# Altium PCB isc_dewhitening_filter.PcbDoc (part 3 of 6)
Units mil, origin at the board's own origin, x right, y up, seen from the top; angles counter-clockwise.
Board outline 8440 x 7000 mil, 6 copper layers (Top Layer, MidLayer1, InternalPlane1, Internal Plane 3, InternalPlane2, Bottom Layer); 550 components, 462 nets, 2189 pads, 795 vias.
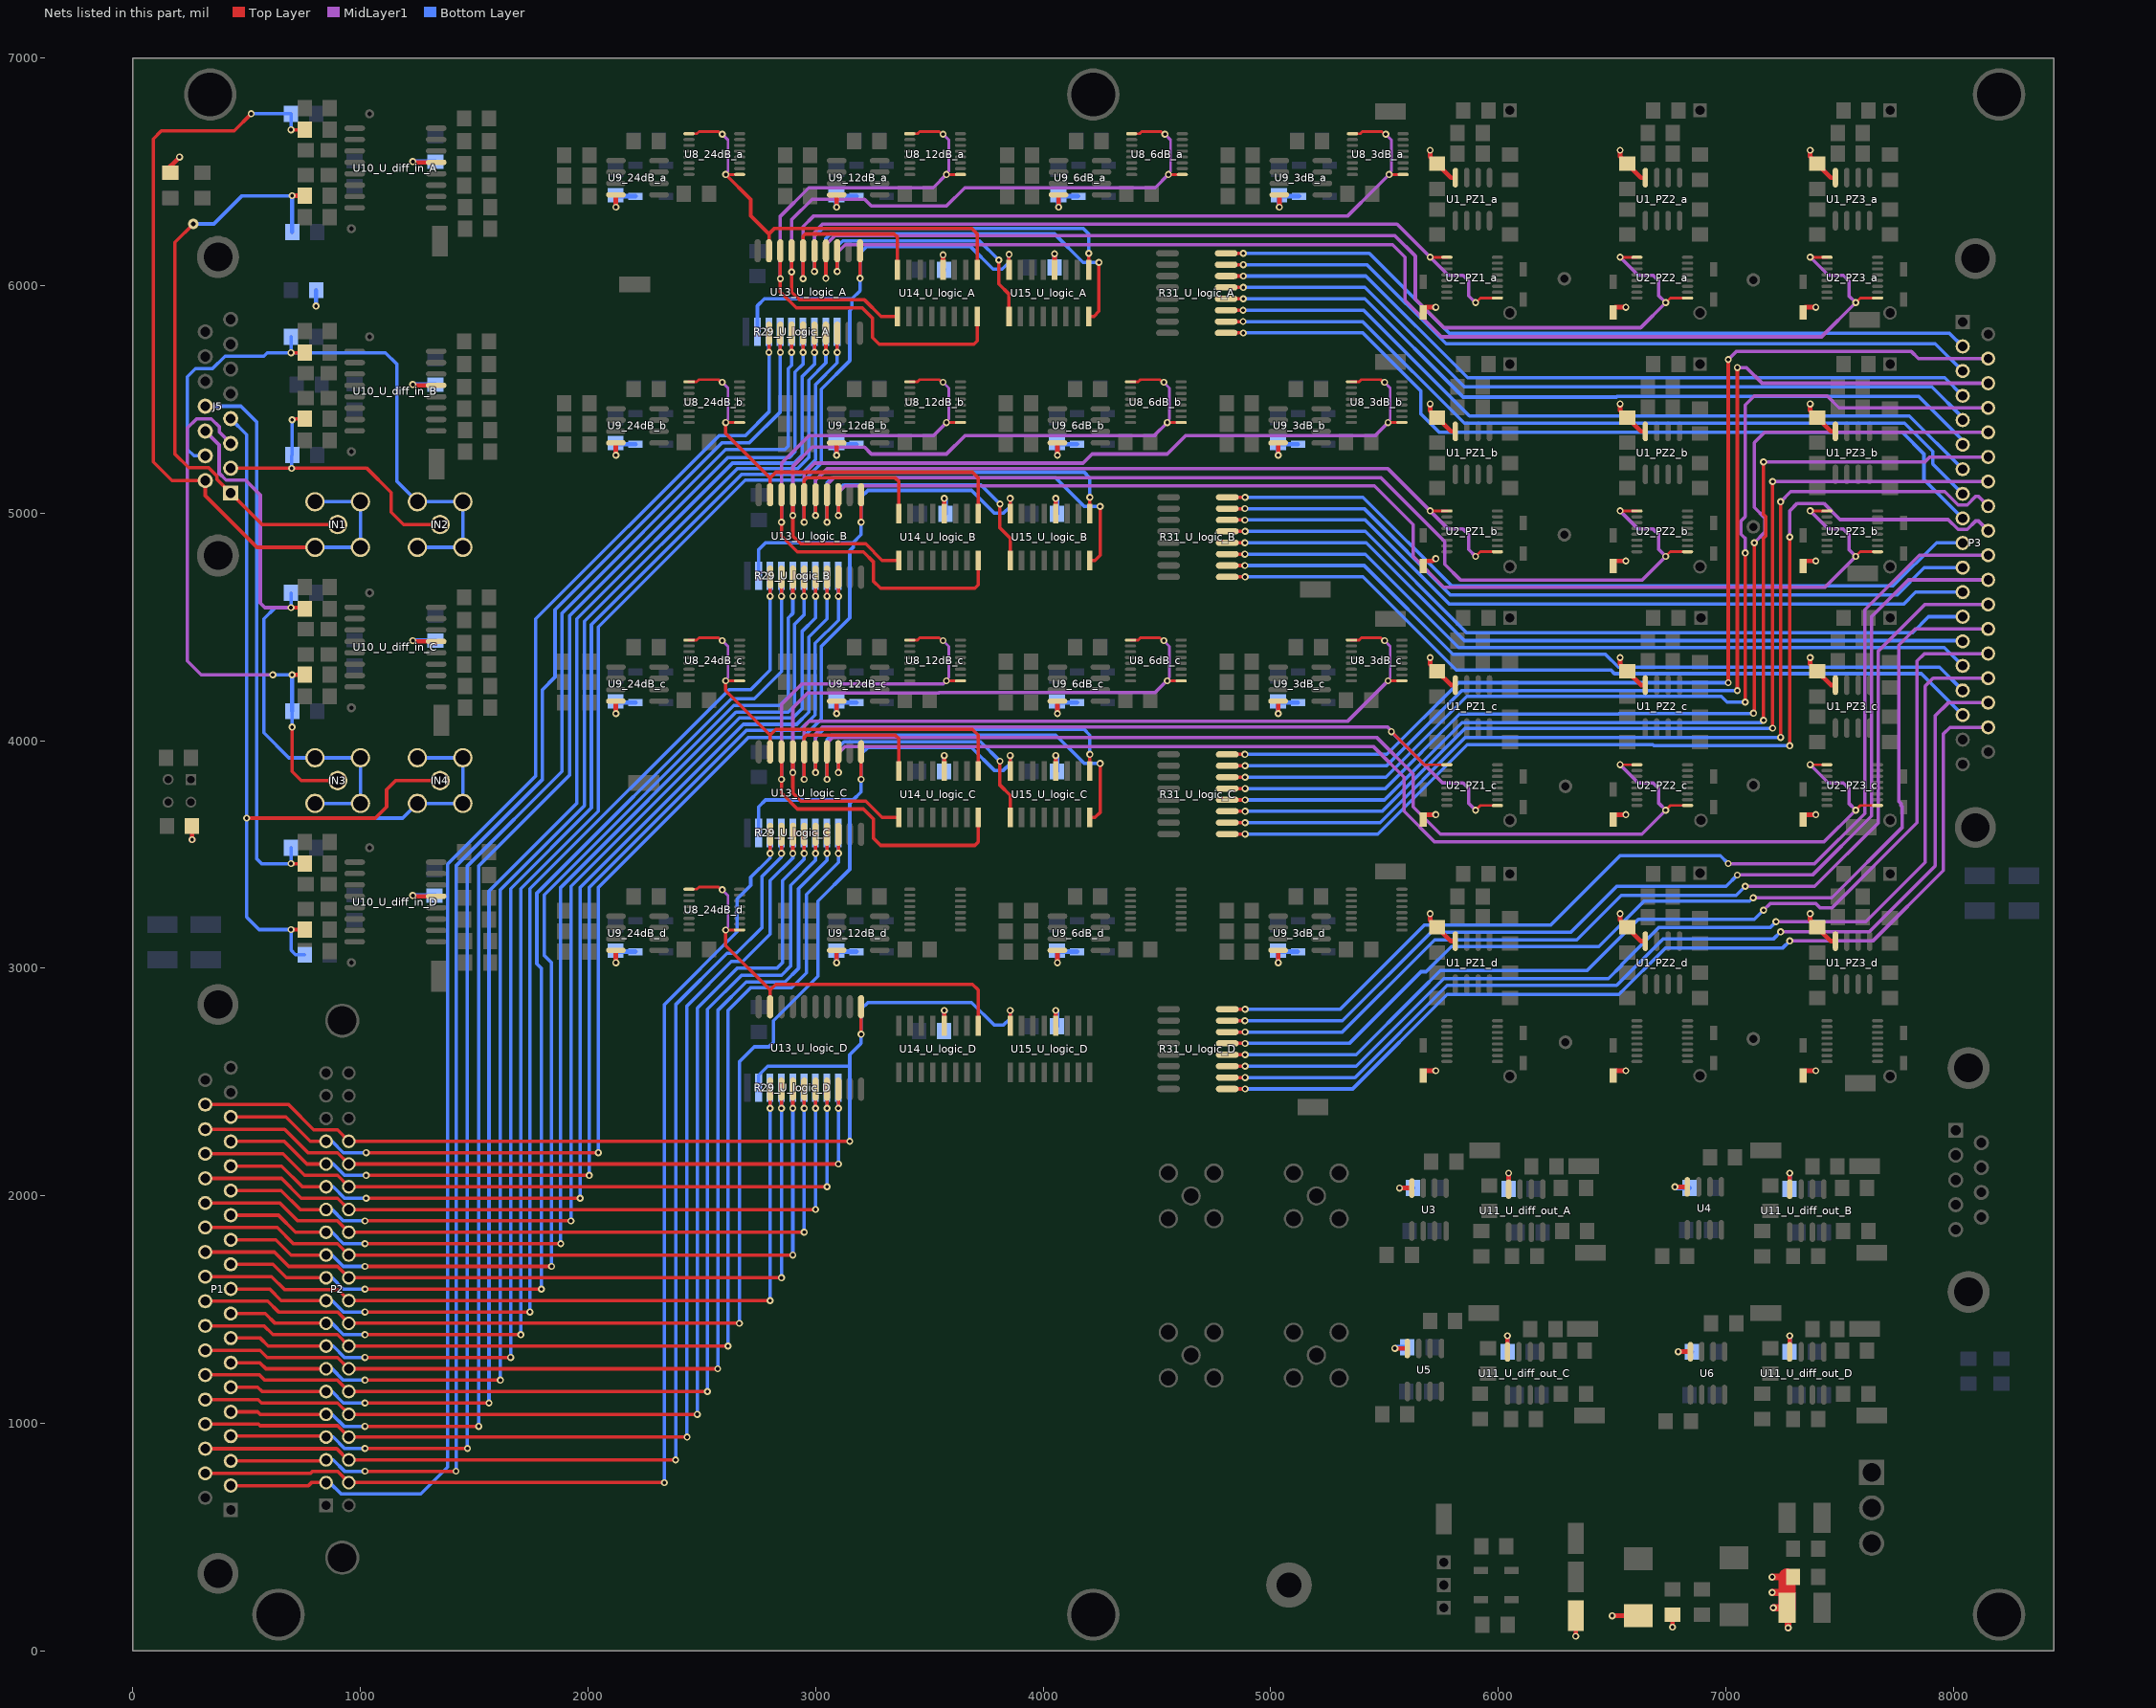
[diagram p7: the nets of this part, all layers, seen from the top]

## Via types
v1: diameter 31, hole 16, Top Layer to Bottom Layer, 794 vias
v2: diameter 45, hole 20, Top Layer to Bottom Layer, 1 vias

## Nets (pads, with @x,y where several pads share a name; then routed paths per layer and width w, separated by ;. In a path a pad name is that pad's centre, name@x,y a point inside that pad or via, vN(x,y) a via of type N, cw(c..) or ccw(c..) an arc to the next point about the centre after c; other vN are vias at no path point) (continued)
-15: C1_PZ1_a.2 C1_PZ1_b.2 C1_PZ1_c.2 C1_PZ1_d.2 C1_PZ2_a.2 C1_PZ2_b.2 C1_PZ2_c.2 C1_PZ2_d.2 C1_PZ3_a.2 C1_PZ3_b.2 C1_PZ3_c.2 C1_PZ3_d.2 C6.2 C9.2 C12.2 C15.2 C22.1 C23.2 C24_3dB_a.2 C24_3dB_b.2 C24_3dB_c.2 C24_3dB_d.2 C24_6dB_a.2 C24_6dB_b.2 C24_6dB_c.2 C24_6dB_d.2 C24_12dB_a.2 C24_12dB_b.2 C24_12dB_c.2 C24_12dB_d.2 C24_24dB_a.2 C24_24dB_b.2 C24_24dB_c.2 C24_24dB_d.2 C29_U_diff_in_A.1 C29_U_diff_in_B.1 C29_U_diff_in_C.1 C29_U_diff_in_D.1 C31_U_diff_out_A.1 C31_U_diff_out_B.1 C31_U_diff_out_C.1 C31_U_diff_out_D.1 C32_U_logic_A.2 C32_U_logic_B.2 C32_U_logic_C.2 C32_U_logic_D.2 C36_U_logic_A.2 C36_U_logic_B.2 C36_U_logic_C.2 C36_U_logic_D.2 D1_PZ1_a.2 D1_PZ1_b.2 D1_PZ1_c.2 D1_PZ1_d.2 D1_PZ2_a.2 D1_PZ2_b.2 D1_PZ2_c.2 D1_PZ2_d.2 D1_PZ3_a.2 D1_PZ3_b.2 D1_PZ3_c.2 D1_PZ3_d.2 D6_3dB_a.2 D6_3dB_b.2 D6_3dB_c.2 D6_3dB_d.2 D6_6dB_a.2 D6_6dB_b.2 D6_6dB_c.2 D6_6dB_d.2 D6_12dB_a.2 D6_12dB_b.2 D6_12dB_c.2 D6_12dB_d.2 D6_24dB_a.2 D6_24dB_b.2 D6_24dB_c.2 D6_24dB_d.2 L2.2 R8.2 R9.2 R36.1 R39.2 TP6.1 U1_PZ1_a.4 U1_PZ1_b.4 U1_PZ1_c.4 U1_PZ1_d.4 U1_PZ2_a.4 U1_PZ2_b.4 U1_PZ2_c.4 U1_PZ2_d.4 U1_PZ3_a.4 U1_PZ3_b.4 U1_PZ3_c.4 U1_PZ3_d.4 U3.4 U4.4 U5.4 U6.4 U9_3dB_a.4 U9_3dB_b.4 U9_3dB_c.4 U9_3dB_d.4 U9_6dB_a.4 U9_6dB_b.4 U9_6dB_c.4 U9_6dB_d.4 U9_12dB_a.4 U9_12dB_b.4 U9_12dB_c.4 U9_12dB_d.4 U9_24dB_a.4 U9_24dB_b.4 U9_24dB_c.4 U9_24dB_d.4 U10_U_diff_in_A.13 U10_U_diff_in_B.13 U10_U_diff_in_C.13 U10_U_diff_in_D.13 U11_U_diff_out_A.4 U11_U_diff_out_B.4 U11_U_diff_out_C.4 U11_U_diff_out_D.4 U14_U_logic_A.4 U14_U_logic_B.4 U14_U_logic_C.4 U14_U_logic_D.4 U15_U_logic_A.4 U15_U_logic_B.4 U15_U_logic_C.4 U15_U_logic_D.4 | length 9805.2
  Top Layer w20: R8.2@165,6495.12 165,6525 v1(205,6565) ; v1(260.12,3565.12) R9.2@260.12,3625 ; v1(1230,3320) 1233.5,3316.5 U10_U_diff_in_D.13@1332.8,3316.5 ; v1(1230,4440) 1233.5,4436.5 U10_U_diff_in_C.13@1332.8,4436.5 ; v1(1230,5565) 1233.5,5561.5 U10_U_diff_in_B.13@1332.8,5561.5 ; v1(1230,6545) 1233.5,6541.5 U10_U_diff_in_A.13@1332.8,6541.5 ; v1@2121,3023 v1(2122.51,3024.51) U9_24dB_d.4@2122.51,3079 ; v1@2121,4118 v1(2122.51,4119.51) U9_24dB_c.4@2122.51,4174 ; v1@2121,5253 v1(2122.51,5254.51) U9_24dB_b.4@2122.51,5309 ; v1@2121,6343 v1(2122.51,6344.51) U9_24dB_a.4@2122.51,6399 ; v1@3091,3023 v1(3092.51,3024.51) U9_12dB_d.4@3092.51,3079 ; v1@3091,4118 v1(3092.51,4119.51) U9_12dB_c.4@3092.51,4174 ; v1@3091,5253 v1(3092.51,5254.51) U9_12dB_b.4@3092.51,5309 ; v1@3091,6343 v1(3092.51,6344.51) U9_12dB_a.4@3092.51,6399 ; U14_U_logic_A.4@3560,6069.36 v1(3560,6135) ; U14_U_logic_D.4@3565,2747.36 v1(3565,2815) ; U14_U_logic_C.4@3565,3867.36 v1(3565,3935) ; U14_U_logic_B.4@3565,4997.36 v1(3565,5065) ; U15_U_logic_A.4@4050,6069.36 v1(4050,6140) ; U15_U_logic_D.4@4055,2747.36 v1(4055,2815) ; U15_U_logic_C.4@4055,3867.36 v1(4055,3935) ; U15_U_logic_B.4@4055,4997.36 v1(4055,5065) ; v1@4061,3023 v1(4062.51,3024.51) U9_6dB_d.4@4062.51,3079 ; v1@4061,4118 v1(4062.51,4119.51) U9_6dB_c.4@4062.51,4174 ; v1@4061,5253 v1(4062.51,5254.51) U9_6dB_b.4@4062.51,5309 ; v1@4066,6343 v1(4067.51,6344.51) U9_6dB_a.4@4067.51,6399 ; v1@5031,3023 v1(5032.51,3024.51) U9_3dB_d.4@5032.51,3079 ; v1@5031,4118 v1(5032.51,4119.51) U9_3dB_c.4@5032.51,4174 ; v1@5031,5253 v1(5032.51,5254.51) U9_3dB_b.4@5032.51,5309 ; v1@5036,6343 v1(5037.51,6344.51) U9_3dB_a.4@5037.51,6399 ; v1@5545.51,1329.49 U5.4@5600,1329.49 ; v1@5565,2035 v1(5565.51,2034.49) U3.4@5620,2034.49 ; D1_PZ1_d.2@5678.07,2550 v1(5725,2550) ; D1_PZ1_c.2@5678.07,3675 v1(5725,3675) ; D1_PZ1_b.2@5678.07,4790 5712.02,4790 5722.02,4800 v1(5725,4800) ; D1_PZ1_a.2@5678.07,5905 v1(5725,5905) ; v1(5700,3240) 5700,3211.12 C1_PZ1_d.2@5731,3180.12 5791.63,3119.49 U1_PZ1_d.4@5811,3119.49 ; v1(5700,4365) 5700,4336.12 C1_PZ1_c.2@5731,4305.12 5791.63,4244.49 U1_PZ1_c.4@5811,4244.49 ; v1(5700,5480) 5700,5451.12 C1_PZ1_b.2@5731,5420.12 5791.63,5359.49 U1_PZ1_b.4@5811,5359.49 ; v1(5700,6595) 5700,6566.12 C1_PZ1_a.2@5731,6535.12 5791.63,6474.49 U1_PZ1_a.4@5811,6474.49 ; U11_U_diff_out_C.4@6040,1314.49 v1(6040,1385) ; U11_U_diff_out_A.4@6045,2029.49 v1(6045,2100) ; v1(6340,65) TP6.1@6340,155 ; v1(6500,155) C23.2@6615,155 ; D1_PZ2_d.2@6513.07,2550 v1(6560,2550) ; D1_PZ2_c.2@6513.07,3675 v1(6560,3675) ; D1_PZ2_b.2@6513.07,4790 v1(6560,4790) ; D1_PZ2_a.2@6513.07,5905 v1(6560,5905) ; v1(6535,3240) 6535,3211.12 C1_PZ2_d.2@6566,3180.12 6626.63,3119.49 U1_PZ2_d.4@6646,3119.49 ; v1(6535,4365) 6535,4336.12 C1_PZ2_c.2@6566,4305.12 6626.63,4244.49 U1_PZ2_c.4@6646,4244.49 ; v1(6535,5480) 6535,5451.12 C1_PZ2_b.2@6566,5420.12 6626.63,5359.49 U1_PZ2_b.4@6646,5359.49 ; v1(6535,6595) 6535,6566.12 C1_PZ2_a.2@6566,6535.12 6626.63,6474.49 U1_PZ2_a.4@6646,6474.49 ; v1(6765,105) C22.1@6765,159.88 ; v1@6775,2040 v1(6775.51,2039.49) U4.4@6830,2039.49 ; v1@6790,1315 v1(6790.49,1315.49) U6.4@6844,1315.49 ; U11_U_diff_out_D.4@7280,1314.49 v1(7280,1385) ; U11_U_diff_out_B.4@7280,2029.49 v1(7280,2100) ; D1_PZ3_d.2@7348.07,2550 v1(7395,2550) ; D1_PZ3_c.2@7348.07,3675 v1(7395,3675) ; D1_PZ3_b.2@7348.07,4790 v1(7395,4790) ; D1_PZ3_a.2@7348.07,5905 v1(7395,5905) ; v1(7370,3240) 7370,3211.12 C1_PZ3_d.2@7401,3180.12 7461.63,3119.49 U1_PZ3_d.4@7481,3119.49 ; v1(7370,4365) 7370,4336.12 C1_PZ3_c.2@7401,4305.12 7461.63,4244.49 U1_PZ3_c.4@7481,4244.49 ; v1(7370,5480) 7370,5451.12 C1_PZ3_b.2@7401,5420.12 7461.63,5359.49 U1_PZ3_b.4@7481,5359.49 ; v1(7370,6595) 7370,6566.12 C1_PZ3_a.2@7401,6535.12 7461.63,6474.49 U1_PZ3_a.4@7481,6474.49
  Top Layer w30: v1@260,3565 v1(260.12,3565.12) ; v1(7203.11,257.5) 7268.23,257.5 ; v1(7203.11,325) R39.2@7294.88,325 ; v1(7208.11,190) 7273.23,190 v1(7273.23,101.77)
  Top Layer w75: L2.2@7268.23,190 R39.2@7268.23,325
  Bottom Layer w20: v1@805.12,5910.12 R36.1@805.12,5980 ; v1(1230,3320) 1230.12,3319.88 C29_U_diff_in_D.1@1330,3319.88 ; v1(1230,4440) 1230.12,4439.88 C29_U_diff_in_C.1@1330,4439.88 ; v1(1230,5565) 1230.12,5564.88 C29_U_diff_in_B.1@1330,5564.88 ; v1(1230,6545) 1230.12,6544.88 C29_U_diff_in_A.1@1330,6544.88 ; v1(2122.51,3024.51) 2121,3026.02 C24_24dB_d.2@2121,3077.88 2125.88,3073 D6_24dB_d.2@2209.07,3073 ; v1(2122.51,4119.51) 2121,4121.02 C24_24dB_c.2@2121,4172.88 2125.88,4168 D6_24dB_c.2@2209.07,4168 ; v1(2122.51,5254.51) 2121,5256.02 C24_24dB_b.2@2121,5307.88 2125.88,5303 D6_24dB_b.2@2209.07,5303 ; v1(2122.51,6344.51) 2121,6346.02 C24_24dB_a.2@2121,6397.88 2125.88,6393 D6_24dB_a.2@2209.07,6393 ; v1(3092.51,3024.51) 3091,3026.02 C24_12dB_d.2@3091,3077.88 3095.88,3073 D6_12dB_d.2@3179.07,3073 ; v1(3092.51,4119.51) 3091,4121.02 C24_12dB_c.2@3091,4172.88 3095.88,4168 D6_12dB_c.2@3179.07,4168 ; v1(3092.51,5254.51) 3091,5256.02 C24_12dB_b.2@3091,5307.88 3095.88,5303 D6_12dB_b.2@3179.07,5303 ; v1(3092.51,6344.51) 3091,6346.02 C24_12dB_a.2@3091,6397.88 3095.88,6393 D6_12dB_a.2@3179.07,6393 ; v1(3560,6135) 3560,6075.12 C32_U_logic_A.2@3565.12,6070 ; v1(3565,2815) v1@3565.12,2814.88 ; v1(3565,5065) 3570.12,5059.88 C32_U_logic_B.2@3570.12,4997.36 ; C32_U_logic_D.2@3565.12,2725 v1@3565.12,2814.88 ; C32_U_logic_C.2@3565.12,3865 v1@3565.12,3934.88 ; v1@3570.12,2809.88 v1@3565.12,2814.88 ; v1(4050,6140) 4050.12,6139.88 C36_U_logic_A.2@4050.12,6070 ; v1(4055,2815) 4060.12,2809.88 C36_U_logic_D.2@4060.12,2745 ; v1(4055,3935) 4060.12,3929.88 C36_U_logic_C.2@4060.12,3865 ; v1(4055,5065) 4060.12,5059.88 C36_U_logic_B.2@4060.12,4997.36 ; v1(4062.51,3024.51) 4061,3026.02 C24_6dB_d.2@4061,3077.88 4065.88,3073 D6_6dB_d.2@4149.07,3073 ; v1(4062.51,4119.51) 4061,4121.02 C24_6dB_c.2@4061,4172.88 4065.88,4168 D6_6dB_c.2@4149.07,4168 ; v1(4062.51,5254.51) 4061,5256.02 C24_6dB_b.2@4061,5307.88 4065.88,5303 D6_6dB_b.2@4149.07,5303 ; v1(4067.51,6344.51) 4066,6346.02 C24_6dB_a.2@4066,6397.88 4070.88,6393 D6_6dB_a.2@4154.07,6393 ; v1(5032.51,3024.51) 5031,3026.02 C24_3dB_d.2@5031,3077.88 5035.88,3073 D6_3dB_d.2@5119.07,3073 ; v1(5032.51,4119.51) 5031,4121.02 C24_3dB_c.2@5031,4172.88 5035.88,4168 D6_3dB_c.2@5119.07,4168 ; v1(5032.51,5254.51) 5031,5256.02 C24_3dB_b.2@5031,5307.88 5035.88,5303 D6_3dB_b.2@5119.07,5303 ; v1(5037.51,6344.51) 5036,6346.02 C24_3dB_a.2@5036,6397.88 5040.88,6393 D6_3dB_a.2@5124.07,6393 ; v1(5545,1330) 5550,1335 C12.2@5599.88,1335 ; v1(5565.51,2034.49) 5566.02,2035 C6.2@5624.88,2035 ; C31_U_diff_out_C.1@6039.88,1315 6039.88,1384.88 v1(6040,1385) ; C31_U_diff_out_A.1@6044.88,2030 6044.88,2099.88 v1(6045,2100) ; v1(6775.51,2039.49) 6780,2035 C9.2@6839.88,2035 ; v1(6790.49,1315.49) 6790.98,1315 C15.2@6849.88,1315 ; C31_U_diff_out_D.1@7279.88,1315 7279.88,1384.88 v1(7280,1385) ; C31_U_diff_out_B.1@7279.88,2030 7279.88,2099.88 v1(7280,2100)
  other v1: 805,5910
A1: U8_24dB_a.1 U8_24dB_a.9 U13_U_logic_A.19 U14_U_logic_A.1 | length 1914.8
  Top Layer w12: U8_24dB_a.9@2443.78,6667.36 2443.95,6667.53 2477.87,6667.53 2487.34,6677 2572.86,6677 2584.86,6665 v1(2590,6665) ; v1(2605,6488.23) U8_24dB_a.1@2666.22,6488.23
  Top Layer w15: v1(2605,6488.23) 2715,6378.23 2715,6307 2795,6227 ; U13_U_logic_A.19@2795,6153.1 2795,6227 ; U14_U_logic_A.1@3710,6069.36 3710,6227 3685,6252 2820,6252 2795,6227
  MidLayer1 w12: v1(2590,6665) 2615,6640 2615,6503.37 2605,6493.37 v1(2605,6488.23)
A2: U8_12dB_a.1 U8_12dB_a.9 U13_U_logic_A.18 U14_U_logic_A.16 | length 2793.6
  Top Layer w12: U8_12dB_a.9@3413.78,6667.36 3413.95,6667.53 3447.87,6667.53 3457.34,6677 3542.86,6677 3554.86,6665 v1(3560,6665) ; v1(3575,6488.23) U8_12dB_a.1@3636.22,6488.23
  Top Layer w15: U13_U_logic_A.18@2845,6153.1 v1(2845,6030) 2845,5972 2915,5902 3205,5902 3250,5857 3250,5772 3280,5742 3695,5742 3710,5757 U14_U_logic_A.16@3710,5864.64
  MidLayer1 w12: v1(3560,6665) 3585,6640 3585,6503.37 3575,6493.37 v1(3575,6488.23)
  MidLayer1 w15: v1(2845,6030) 2845,6305 2970,6430 3516.77,6430 v1(3575,6488.23)
A3: U8_6dB_a.1 U8_6dB_a.9 U13_U_logic_A.17 U14_U_logic_A.9 | length 3090.2
  Top Layer w12: U8_6dB_a.9@4388.78,6667.36 4388.95,6667.53 4422.87,6667.53 4432.34,6677 4517.86,6677 4529.86,6665 v1(4535,6665) ; v1(4550,6488.23) U8_6dB_a.1@4611.22,6488.23
  Top Layer w15: U13_U_logic_A.17@2895,6153.1 v1(2895,6060) 2895,5972 2930,5937 3215,5937 3287.36,5864.64 U14_U_logic_A.9@3360,5864.64
  MidLayer1 w12: v1(4535,6665) 4560,6640 4560,6503.37 4550,6493.37 v1(4550,6488.23)
  MidLayer1 w15: v1(2895,6060) 2895,6290 2985,6380 3215,6380 3245,6350 3575,6350 3655,6430 4491.77,6430 v1(4550,6488.23)
A4: U8_3dB_a.1 U8_3dB_a.9 U13_U_logic_A.16 U14_U_logic_A.8 | length 4062.2
  Top Layer w12: U8_3dB_a.9@5358.78,6667.36 5358.95,6667.53 5392.87,6667.53 5402.34,6677 5487.86,6677 5499.86,6665 v1(5505,6665) ; v1(5520,6488.23) U8_3dB_a.1@5581.22,6488.23
  Top Layer w15: v1(2945,6030) U13_U_logic_A.16@2945,6153.1 2945,6217 2955,6227 3345,6227 3360,6212 U14_U_logic_A.8@3360,6069.36
  MidLayer1 w12: v1(5505,6665) 5530,6640 5530,6503.37 5520,6493.37 v1(5520,6488.23)
  MidLayer1 w15: v1(2945,6030) 2945,6260 2990,6305 5336.77,6305 5461.77,6430 v1(5520,6488.23)
A5: U2_PZ1_a.1 U2_PZ1_a.9 U13_U_logic_A.15 U15_U_logic_A.1 | length 5085.7
  Top Layer w12: v1(5700,6125) 5700.43,6124.57 U2_PZ1_a.1@5773.78,6124.57 ; v1(5900,5925) 5920.43,5945.43 U2_PZ1_a.9@5996.22,5945.43
  Top Layer w15: v1(2995,6062) U13_U_logic_A.15@2995,6153.1 ; U15_U_logic_A.1@4200,6069.36 v1(4200,6142)
  MidLayer1 w15: v1(2995,6062) 2995,6235 3030,6270 5555,6270 v1(5700,6125) 5780,6045 5845,6045 5870,6020 5870,5955 v1(5900,5925)
  Bottom Layer w15: v1(2995,6062) 2995,6217 3030,6252 4175,6252 4200,6227 v1(4200,6142)
A6: U2_PZ2_a.1 U2_PZ2_a.9 U13_U_logic_A.14 U15_U_logic_A.16 | length 6504.2
  Top Layer w12: v1(6535,6125) 6535.43,6124.57 U2_PZ2_a.1@6608.78,6124.57 ; v1(6735,5925) 6755.43,5945.43 U2_PZ2_a.9@6831.22,5945.43
  Top Layer w15: v1(3045,6032) U13_U_logic_A.14@3045,6153.1 ; U15_U_logic_A.16@4200,5864.64 4222.64,5864.64 4245,5887 v1(4245,6102)
  MidLayer1 w15: v1(3045,6032) 3045,6180 3085,6220 5545,6220 5635,6130 5635,5940 5760,5815 6625,5815 v1(6735,5925) 6705,5955 6705,6020 6680,6045 6615,6045 v1(6535,6125)
  Bottom Layer w15: v1(3045,6032) 3045,6207 3065,6227 4050,6227 4175,6102 v1(4245,6102)
A7: U2_PZ3_a.1 U2_PZ3_a.9 U13_U_logic_A.13 U15_U_logic_A.9 | length 6635.9
  Top Layer w12: v1(7370,6125) 7370.43,6124.57 U2_PZ3_a.1@7443.78,6124.57 ; v1(7570,5925) 7590.43,5945.43 U2_PZ3_a.9@7666.22,5945.43
  Top Layer w15: v1(3095,6062) U13_U_logic_A.13@3095,6153.1 ; v1(3805,6112) 3805,6007 3850,5962 U15_U_logic_A.9@3850,5864.64
  MidLayer1 w15: v1(3095,6062) 3095,6145 3130,6180 5535,6180 5590,6125 5590,5935 5750,5775 7420,5775 v1(7570,5925) 7540,5955 7540,6020 7515,6045 7450,6045 v1(7370,6125)
  Bottom Layer w15: v1(3095,6062) 3095,6172 3120,6197 3720,6197 v1(3805,6112)
AN_1: IN1.2 J5.9 R22_U_diff_in_A.1 R33_U_diff_in_A.2 | length 3704.2
  Top Layer w15: v1(520,6755) 445,6680 125,6680 90,6645 90,5225 172.17,5142.83 J5.9@318.11,5142.83 318.11,5076.89 545,4850 IN1.2@800,4850 ; v1(695,6685) R33_U_diff_in_A.2@754.88,6685
  Bottom Layer w15: v1(520,6755) R22_U_diff_in_A.1@694.88,6755 ; v1(695,6685) R22_U_diff_in_A.1@695,6754.88 ; IN1.2@800,4850 IN1.2@1000,4850 IN1.2@1000,5050 IN1.2@800,5050
AN_2: IN2.2 J5.10 R22_U_diff_in_B.1 R33_U_diff_in_B.2 | length 2766
  Top Layer w15: v1(695,5705) R33_U_diff_in_B.2@754.88,5705
  Bottom Layer w15: J5.10@318.11,5251.89 268.11,5251.89 240,5280 240,5600 275,5635 350,5635 405,5690 575,5690 590,5705 v1(695,5705) ; R22_U_diff_in_B.1@695,5774.88 v1(695,5705) ; IN2.2@1250,4850 IN2.2@1450,4850 IN2.2@1450,5050 IN2.2@1250,5050 1160,5140 1160,5655 1110,5705 v1(695,5705)
AN_3: IN3.2 J5.11 R22_U_diff_in_C.1 R33_U_diff_in_C.2 | length 2687.5
  Top Layer w15: v1(695,4585) 749.88,4585 R33_U_diff_in_C.2@754.88,4580
  MidLayer1 w15: J5.11@318.11,5360.94 379.15,5299.9 379.15,5175.49 409.64,5145 495,5145 560,5080 560,4605 580,4585 v1(695,4585)
  Bottom Layer w15: R22_U_diff_in_C.1@695,4649.88 v1(695,4585) 625,4585 575,4535 575,4035 685,3925 IN3.2@800,3925 IN3.2@1000,3925 IN3.2@1000,3725 IN3.2@800,3725
AN_4: IN4.2 J5.12 R22_U_diff_in_D.1 R33_U_diff_in_D.2 | length 3795.9
  Top Layer w15: v1(695,3460) R33_U_diff_in_D.2@754.88,3460
  Bottom Layer w15: J5.12@318.11,5470 475,5470 545,5400 545,3480 565,3460 v1(695,3460) R22_U_diff_in_D.1@695,3529.88 ; 545,3660 1185,3660 IN4.2@1250,3725 IN4.2@1450,3725 IN4.2@1450,3925 IN4.2@1250,3925
AP_1: IN1.1 J5.1 R14_U_diff_in_A.2 R32_U_diff_in_A.2 | length 2596.6
  Top Layer w15: v2(266,6271) 185,6190 185,5260 245,5200 332.74,5200 368.88,5163.86 368.88,5149.35 J5.1@429.92,5088.31 568.23,4950 IN1.1@900,4950
  Top Layer w20: v1(700,6395) R32_U_diff_in_A.2@754.88,6395
  Bottom Layer w15: v2(266,6271) 356,6271 480,6395 v1(700,6395)
  Bottom Layer w20: R14_U_diff_in_A.2@700,6235.12 v1(700,6395)
AP_2: IN2.1 J5.2 R14_U_diff_in_B.2 R32_U_diff_in_B.2 | length 1343.1
  Top Layer w15: J5.2@429.92,5197.36 697.64,5197.36 v1(698,5197) ; v1@698.68,5198.68 1026.32,5198.68 1135,5090 1135,5005 1190,4950 IN2.1@1350,4950 ; v1(700,5410) 705,5415 R32_U_diff_in_B.2@754.88,5415
  Bottom Layer w15: v1(698,5197) 698,5253 700,5255 v1(700,5410)
AP_3: IN3.1 J5.3 R14_U_diff_in_C.2 R32_U_diff_in_C.2 | length 2471.4
  Top Layer w15: v1(700,4060) 700,3865 740,3825 IN3.1@900,3825
  Top Layer w20: v1(700,4290) R32_U_diff_in_C.2@754.88,4290
  MidLayer1 w15: J5.3@429.92,5306.42 380,5356.34 380,5380 345,5415 280,5415 240,5375 240,4350 300,4290 v1(615,4290)
  Bottom Layer w15: v1(615,4290) v1(700,4290) ; v1(700,4060) R14_U_diff_in_C.2@700,4129.88
  Bottom Layer w20: R14_U_diff_in_C.2@700,4130.12 v1(700,4290)
AP_4: IN4.1 J5.4 R14_U_diff_in_D.2 R32_U_diff_in_D.2 | length 3617.6
  Top Layer w15: v1(500,3660) 1065,3660 1115,3710 1115,3785 1155,3825 IN4.1@1350,3825 ; v1(695,3170) R32_U_diff_in_D.2@754.88,3170
  Bottom Layer w15: J5.4@429.92,5415.47 500,5345.39 v1(500,3660) 500,3225 555,3170 v1(695,3170) 695,3080 715,3060 R14_U_diff_in_D.2@754.88,3060
B1: U8_24dB_b.1 U8_24dB_b.9 U13_U_logic_B.19 U14_U_logic_B.1 | length 1898.9
  Top Layer w12: U8_24dB_b.9@2443.78,5577.36 2443.95,5577.53 2477.87,5577.53 2487.34,5587 2572.86,5587 2584.86,5575 v1(2590,5575) ; v1(2605,5398.23) U8_24dB_b.1@2666.22,5398.23
  Top Layer w15: v1(2605,5398.23) 2605,5350 2800,5155 ; U13_U_logic_B.19@2800,5081.1 2800,5155 ; U14_U_logic_B.1@3715,4997.36 3715,5155 3690,5180 2825,5180 2800,5155
  MidLayer1 w12: v1(2590,5575) 2615,5550 2615,5413.37 2605,5403.37 v1(2605,5398.23)
B2: U8_12dB_b.1 U8_12dB_b.9 U13_U_logic_B.18 U14_U_logic_B.16 | length 2771.5
  Top Layer w12: U8_12dB_b.9@3413.78,5577.36 3413.95,5577.53 3447.87,5577.53 3457.34,5587 3542.86,5587 3554.86,5575 v1(3560,5575) ; v1(3575,5398.23) U8_12dB_b.1@3636.22,5398.23
  Top Layer w15: U13_U_logic_B.18@2850,5081.1 v1(2850,4960) 2850,4900 2920,4830 3210,4830 3255,4785 3255,4700 3285,4670 3700,4670 3715,4685 U14_U_logic_B.16@3715,4792.64
  MidLayer1 w12: v1(3560,5575) 3585,5550 3585,5413.37 3575,5403.37 v1(3575,5398.23)
  MidLayer1 w15: v1(2850,4960) 2850,5220 2897.5,5267.5 2970,5340 3516.77,5340 v1(3575,5398.23)
B3: U8_6dB_b.1 U8_6dB_b.9 U13_U_logic_B.17 U14_U_logic_B.9 | length 3614.9
  Top Layer w12: U8_6dB_b.9@4383.78,5577.36 4383.95,5577.53 4417.87,5577.53 4427.34,5587 4512.86,5587 4524.86,5575 v1(4530,5575) ; v1(4545,5398.23) U8_6dB_b.1@4606.22,5398.23
  Top Layer w15: U13_U_logic_B.17@2900,5081.1 v1(2900,4990) 2900,4900 2935,4865 3220,4865 3292.36,4792.64 U14_U_logic_B.9@3365,4792.64
  MidLayer1 w12: v1(4530,5575) 4555,5550 4555,5413.37 4545,5403.37 v1(4545,5398.23)
  MidLayer1 w15: v1(2900,4990) 2900,5205 2985,5290 3215,5290 3245,5260 3575,5260 3655,5340 4491.77,5340 ; 3940,5340 4486.77,5340 v1(4545,5398.23)
B4: U8_3dB_b.1 U8_3dB_b.9 U13_U_logic_B.16 U14_U_logic_B.8 | length 4584.9
  Top Layer w12: U8_3dB_b.9@5353.78,5577.36 5353.95,5577.53 5387.87,5577.53 5397.34,5587 5482.86,5587 5494.86,5575 v1(5500,5575) ; v1(5515,5398.23) U8_3dB_b.1@5576.22,5398.23
  Top Layer w15: v1(2950,4960) U13_U_logic_B.16@2950,5081.1 2950,5145 2960,5155 3350,5155 3365,5140 U14_U_logic_B.8@3365,4997.36
  MidLayer1 w12: v1(5500,5575) 5525,5550 5525,5413.37 5515,5403.37 v1(5515,5398.23)
  MidLayer1 w15: v1(2950,4960) 2950,5175 2995,5220 4175,5220 4215,5260 4545,5260 4625,5340 5456.77,5340 ; 4910,5340 5456.77,5340 ; 5461.77,5340 5456.77,5340 ; v1(5515,5398.23) 5456.77,5340
B5: U2_PZ1_b.1 U2_PZ1_b.9 U13_U_logic_B.15 U15_U_logic_B.1 | length 5085.5
  Top Layer w12: v1(5700,5010) 5700.43,5009.57 U2_PZ1_b.1@5773.78,5009.57 ; v1(5900,4810) 5920.43,4830.43 U2_PZ1_b.9@5996.22,4830.43
  Top Layer w15: v1(3000,4990) U13_U_logic_B.15@3000,5081.1 ; U15_U_logic_B.1@4205,4997.36 v1(4205,5070)
  MidLayer1 w15: v1(3000,4990) 3000,5145 3050,5195 5515,5195 v1(5700,5010) 5780,4930 5845,4930 5870,4905 5870,4840 v1(5900,4810)
  Bottom Layer w15: v1(3000,4990) 3000,5145 3035,5180 4180,5180 4205,5155 v1(4205,5070)
B6: U2_PZ2_b.1 U2_PZ2_b.9 U13_U_logic_B.14 U15_U_logic_B.16 | length 6475.9
  Top Layer w12: v1(6535,5010) 6535.43,5009.57 U2_PZ2_b.1@6608.78,5009.57 ; v1(6735,4810) 6755.43,4830.43 U2_PZ2_b.9@6831.22,4830.43
  Top Layer w15: v1(3050,4960) U13_U_logic_B.14@3050,5081.1 ; U15_U_logic_B.16@4205,4792.64 4227.64,4792.64 4250,4815 v1(4250,5030)
  MidLayer1 w15: v1(3050,4960) 3050,5125 3080,5155 5485,5155 5765,4875 5765,4775 5835,4705 6630,4705 v1(6735,4810) 6705,4840 6705,4905 6680,4930 6615,4930 v1(6535,5010)
  Bottom Layer w15: v1(3050,4960) 3050,5135 3070,5155 4055,5155 4180,5030 v1(4250,5030)
B7: U2_PZ3_b.1 U2_PZ3_b.9 U13_U_logic_B.13 U15_U_logic_B.9 | length 6626.9
  Top Layer w12: v1(7370,5010) 7370.43,5009.57 U2_PZ3_b.1@7443.78,5009.57 ; v1(7570,4810) 7590.43,4830.43 U2_PZ3_b.9@7666.22,4830.43
  Top Layer w15: v1(3100,4990) U13_U_logic_B.13@3100,5081.1 ; v1(3810,5040) 3810,4935 3855,4890 U15_U_logic_B.9@3855,4792.64
  MidLayer1 w15: v1(3100,4990) 3100,5090 3130,5120 5455,5120 5625,4950 5625,4810 5760,4675 7380,4675 7435,4675 v1(7570,4810) 7540,4840 7540,4905 7515,4930 7450,4930 v1(7370,5010)
  Bottom Layer w15: v1(3100,4990) 3100,5100 3125,5125 3725,5125 v1(3810,5040)
BI_0: P1.2 P2.3 R29_U_logic_A.3 U13_U_logic_A.2 | length 6752.5
  Top Layer w15: P1.2@430,727 772,727 785,740 P2.3@849,740 ; v1(2795,5707) U13_U_logic_A.2@2795,5790.9
  Bottom Layer w15: P2.3@849,740 865,740 915,690 1265,690 1382.93,807.93 1382.93,3457.93 1770,3845 1770,4535 2575,5340 2690,5340 2795,5445 v1(2795,5707) ; v1@2794.41,5707.59 R29_U_logic_A.3@2794.41,5797
BI_1: P1.3 P2.5 R29_U_logic_A.4 U13_U_logic_A.3 | length 6763.6
  Top Layer w15: P1.3@430,835 844,835 P2.5@849,840 ; v1(1020,790) v1(1420,790) ; v1(2845,5707) U13_U_logic_A.3@2845,5790.9
  Bottom Layer w15: P2.5@849,840 880,840 930,790 v1(1020,790) ; v1(1420,790) 1420,3450 1800,3830 1800,4225 1855,4280 1855,4575 2590,5310 2710,5310 2845,5445 v1(2845,5707) ; v1@2844.41,5707.59 R29_U_logic_A.4@2844.41,5797
BI_2: P1.4 P2.7 R29_U_logic_A.5 U13_U_logic_A.4 | length 6795.2
  Top Layer w15: P1.4@430,944 845,944 P2.7@849,940 ; v1(1020,890) v1(1470,890) ; v1(2895,5707) U13_U_logic_A.4@2895,5790.9
  Bottom Layer w15: P2.7@849,940 880,940 930,890 v1(1020,890) ; v1(1470,890) 1470,3450 1885,3865 1885,4560 2605,5280 2865,5280 2880,5295 2880,5635 2895,5650 v1(2895,5707) ; v1@2894.41,5707.59 R29_U_logic_A.5@2894.41,5797
BI_3: P1.5 P2.9 R29_U_logic_A.6 U13_U_logic_A.5 | length 6757.5
  Top Layer w15: P1.5@430,1051 549,1051 560,1040 P2.9@849,1040 ; v1(1020,987.5) v1(1520,987.5) ; v1(2945,5707) U13_U_logic_A.5@2945,5790.9
  Bottom Layer w15: P2.9@849,1040 875,1040 927.5,987.5 v1(1020,987.5) ; v1(1520,987.5) 1520,3450 1920,3850 1920,4550 2615,5245 2885,5245 2910,5270 2910,5620 2945,5655 v1(2945,5707) ; v1@2944.41,5707.59 R29_U_logic_A.6@2944.41,5797
BI_4: P1.6 P2.11 R29_U_logic_A.7 U13_U_logic_A.6 | length 6704.4
  Top Layer w15: P1.6@430,1159 549,1159 568,1140 P2.11@849,1140 ; v1(1020,1090) v1(1565,1090) ; v1(2995,5707) U13_U_logic_A.6@2995,5790.9
  Bottom Layer w15: P2.11@849,1140 875,1140 925,1090 v1(1020,1090) ; v1(1565,1090) 1565,3340 1950,3725 1950,4535 2635,5220 2905,5220 2940,5255 2940,5600 2995,5655 v1(2995,5707) ; v1@2994.41,5707.59 R29_U_logic_A.7@2994.41,5797
BI_5: P1.7 P2.13 R29_U_logic_A.8 U13_U_logic_A.7 | length 6654.8
  Top Layer w15: P1.7@430,1267 558,1267 585,1240 P2.13@849,1240 ; v1(1020,1190) v1(1615,1190) ; v1(3045,5707) U13_U_logic_A.7@3045,5790.9
  Bottom Layer w15: P2.13@849,1240 875,1240 925,1190 v1(1020,1190) ; v1(1615,1190) 1615,3345 1984.82,3714.82 1984.82,4524.82 2655,5195 2920,5195 2970,5245 2970,5585 3045,5660 v1(3045,5707) ; v1@3044.41,5707.59 R29_U_logic_A.8@3044.41,5797
BI_6: P1.8 P2.15 R29_U_logic_A.9 U13_U_logic_A.8 | length 6602.2
  Top Layer w15: P1.8@430,1375 560,1375 595,1340 P2.15@849,1340 ; v1(1020,1290) v1(1660,1290) ; v1(3095,5707) U13_U_logic_A.8@3095,5790.9
  Bottom Layer w15: P2.15@849,1340 880,1340 930,1290 v1(1020,1290) ; v1(1660,1290) 1660,3350 2014.82,3704.82 2014.82,4509.82 2675,5170 2935,5170 3000,5235 3000,5565 3095,5660 v1(3095,5707) ; v1@3094.41,5707.59 R29_U_logic_A.9@3094.41,5797
BI_7: P1.9 P2.17 R29_U_logic_A.2 U13_U_logic_A.11 U15_U_logic_A.8 | length 8322.7
  Top Layer w15: P1.9@430,1483 582,1483 625,1440 P2.17@849,1440 ; v1(1020,1390) v1(1705,1390) ; v1(3195,6032) U13_U_logic_A.11@3195,6153.1 ; U15_U_logic_A.8@3850,6069.36 v1(3850,6137)
  Bottom Layer w15: P2.17@849,1440 875,1440 925,1390 v1(1020,1390) ; v1(1705,1390) 1705,3350 2045,3690 2045,4500 2690,5145 2950,5145 3025,5220 3025,5545 3150,5670 3150,5890 3160,5900 3160,5942 ; R29_U_logic_A.2@2744.41,5797 2744.41,5911.41 2775,5942 3160,5942 ; v1(3850,6137) 3850,6102 3820,6072 3780,6072 3680,6172 3225,6172 3195,6142 v1(3195,6032) 3195,5977 3160,5942
BI_8: P1.10 P2.19 R29_U_logic_B.3 U13_U_logic_B.2 | length 5167.8
  Top Layer w15: P1.10@430,1591 601,1591 652,1540 P2.19@849,1540 ; v1(1020,1490) v1(1745,1490) ; v1(2800,4635) U13_U_logic_B.2@2800,4718.9
  Bottom Layer w15: P2.19@849,1540 875,1540 925,1490 v1(1020,1490) ; v1(1745,1490) 1745,3350 2620,4225 2715,4225 2800,4310 v1(2800,4635) ; v1@2799.41,4635.59 R29_U_logic_B.3@2799.41,4725
BI_9: P1.11 P2.21 R29_U_logic_B.4 U13_U_logic_B.3 | length 5140.6
  Top Layer w15: P1.11@430,1699 616,1699 675,1640 P2.21@849,1640 ; v1(1020,1590) v1(1795,1590) ; v1(2850,4635) U13_U_logic_B.3@2850,4718.9
  Bottom Layer w15: P2.21@849,1640 875,1640 925,1590 v1(1020,1590) ; v1(1795,1590) 1795,3000 1775,3020 1775,3330 2630,4185 2730,4185 2850,4305 v1(2850,4635) ; v1@2849.41,4635.59 R29_U_logic_B.4@2849.41,4725
BI_10: P1.12 P2.23 R29_U_logic_B.5 U13_U_logic_B.4 | length 5162.1
  Top Layer w15: P1.12@430,1807 628,1807 695,1740 P2.23@849,1740 ; v1(1020,1690) v1(1840,1690) ; v1(2900,4635) U13_U_logic_B.4@2900,4718.9
  Bottom Layer w15: P2.23@849,1740 875,1740 925,1690 v1(1020,1690) ; v1(1840,1690) 1840,3023.33 1807,3056.33 1807,3322 2640,4155 2843,4155 2880,4192 2880,4540 2900,4560 v1(2900,4635) ; v1@2899.41,4635.59 R29_U_logic_B.5@2899.41,4725
BI_11: P1.13 P2.25 R29_U_logic_B.6 U13_U_logic_B.5 | length 5098
  Top Layer w15: P1.13@430,1915 640,1915 715,1840 P2.25@849,1840 ; v1(1020,1790) v1(1880,1790) ; v1(2950,4635) U13_U_logic_B.5@2950,4718.9
  Bottom Layer w15: P2.25@849,1840 875,1840 925,1790 v1(1020,1790) ; v1(1880,1790) 1880,3355 2650,4125 2880,4125 2908,4153 2908,4513 2950,4555 v1(2950,4635) ; v1@2949.41,4635.59 R29_U_logic_B.6@2949.41,4725
BI_12: P1.14 P2.27 R29_U_logic_B.7 U13_U_logic_B.6 | length 5051.3
  Top Layer w15: P1.14@430,2023 652,2023 735,1940 P2.27@849,1940 ; v1(1020,1890) v1(1925,1890) ; v1(3000,4635) U13_U_logic_B.6@3000,4718.9
  Bottom Layer w15: P2.27@849,1940 875,1940 925,1890 v1(1020,1890) ; v1(1925,1890) 1925,3360 2665,4100 2900,4100 2940,4140 2940,4480 3000,4540 v1(3000,4635) ; v1@2999.41,4635.59 R29_U_logic_B.7@2999.41,4725
BI_13: P1.15 P2.29 R29_U_logic_B.8 U13_U_logic_B.7 | length 4998.8
  Top Layer w15: P1.15@430,2131 654,2131 745,2040 P2.29@849,2040 ; v1(1025,1990) v1(1965,1990) ; v1(3050,4635) U13_U_logic_B.7@3050,4718.9
  Bottom Layer w15: P2.29@849,2040 880,2040 930,1990 v1(1025,1990) ; v1(1965,1990) 1965,3355 2682,4072 2917,4072 2971,4126 2971,4456 3050,4535 v1(3050,4635) ; v1@3049.41,4635.59 R29_U_logic_B.8@3049.41,4725
BI_14: P1.16 P2.31 R29_U_logic_B.9 U13_U_logic_B.8 | length 4951
  Top Layer w15: P1.16@430,2239 666,2239 765,2140 P2.31@849,2140 ; v1(1025,2090) v1(2005,2090) ; v1(3100,4635) U13_U_logic_B.8@3100,4718.9
  Bottom Layer w15: P2.31@849,2140 880,2140 930,2090 v1(1025,2090) ; v1@2005,2085 2005,3355 2695,4045 2929.64,4045 2998,4113.36 2998,4428 3100,4530 v1(3100,4635) ; v1@3099.41,4635.59 R29_U_logic_B.9@3099.41,4725
BI_15: P1.17 P2.33 R29_U_logic_B.2 U13_U_logic_B.11 U15_U_logic_B.8 | length 6666.7
  Top Layer w15: P1.17@430,2347 673,2347 780,2240 P2.33@849,2240 ; v1(1025,2190) v1(2045,2190) ; v1(3200,4960) U13_U_logic_B.11@3200,5081.1 ; U15_U_logic_B.8@3855,4997.36 v1(3855,5065)
  Bottom Layer w15: P2.33@849,2240 875,2240 925,2190 v1(1025,2190) ; v1(2045,2190) 2045,3355 2705,4015 2945,4015 3025,4095 3025,4415 3150,4540 3150,4835 3165,4850 3165,4870 ; R29_U_logic_B.2@2749.41,4725 2749.41,4839.41 2780,4870 3165,4870 ; v1(3855,5065) 3855,5030 3825,5000 3785,5000 3685,5100 3230,5100 3200,5070 v1(3200,4960) 3200,4905 3165,4870
BI_16: P1.21 P2.4 R29_U_logic_C.3 U13_U_logic_C.2 | length 5172.4
  Top Layer w15: P1.21@318,781 781,781 790,790 899,790 P2.4@949,740 v1(2335,740) ; v1(2800,3505) U13_U_logic_C.2@2800,3588.9
  Bottom Layer w15: v1(2335,740) 2335,2840 2655,3160 2655,3305 2715,3365 2715,3400 2800,3485 v1(2800,3505) ; v1@2799.41,3505.59 R29_U_logic_C.3@2799.41,3595
BI_17: P1.22 P2.6 R29_U_logic_C.4 U13_U_logic_C.3 | length 5141.6
  Top Layer w15: P1.22@318,889 896,889 945,840 P2.6@949,840 v1(2385,840) ; v1(2850,3505) U13_U_logic_C.3@2850,3588.9
  Bottom Layer w15: v1(2385,840) 2385,2840 2611.33,3066.33 2651.33,3066.33 2765,3180 2765,3405 2850,3490 v1(2850,3505) ; v1@2849.41,3505.59 R29_U_logic_C.4@2849.41,3595
BI_18: P1.23 P2.8 R29_U_logic_C.5 U13_U_logic_C.4 | length 5100.8
  Top Layer w15: P1.23@318,997 553,997 560,990 899,990 P2.8@949,940 v1(2435,940) ; v1(2900,3505) U13_U_logic_C.4@2900,3588.9
  Bottom Layer w15: v1(2435,940) 2435,2835 2630,3030 2680,3030 2800,3150 2800,3385 2900,3485 v1(2900,3505) ; v1@2899.41,3505.59 R29_U_logic_C.5@2899.41,3595
BI_19: P1.24 P2.10 R29_U_logic_C.6 U13_U_logic_C.5 | length 5125
  Top Layer w15: P1.24@318,1105 550,1105 565,1090 900,1090 949,1041 P2.10@949,1040 v1(2480,1040) ; v1(2950,3505) U13_U_logic_C.5@2950,3588.9
  Bottom Layer w15: v1(2480,1040) 2480,2825 2655,3000 2830,3000 2855,3025 2855,3385 2950,3480 v1(2950,3505) ; v1@2949.41,3505.59 R29_U_logic_C.6@2949.41,3595
BI_20: P1.25 P2.12 R29_U_logic_C.7 U13_U_logic_C.6 | length 5074.8
  Top Layer w15: P1.25@318,1213 557,1213 580,1190 899,1190 P2.12@949,1140 v1(2525,1140) ; v1(3000,3505) U13_U_logic_C.6@3000,3588.9
  Bottom Layer w15: v1(2525,1140) 2525,2820 2675,2970 2850,2970 2890,3010 2890,3365 3000,3475 v1(3000,3505) ; v1@2999.41,3505.59 R29_U_logic_C.7@2999.41,3595
BI_21: P1.26 P2.14 R29_U_logic_C.8 U13_U_logic_C.7 | length 5022.3
  Top Layer w15: P1.26@318,1321 559,1321 590,1290 899,1290 P2.14@949,1240 v1(2570,1240) ; v1(3050,3505) U13_U_logic_C.7@3050,3588.9
  Bottom Layer w15: v1(2570,1240) 2570,2815 2695,2940 2865,2940 2925,3000 2925,3350 3050,3475 v1(3050,3505) ; v1@3049.41,3505.59 R29_U_logic_C.8@3049.41,3595
BI_22: P1.27 P2.16 R29_U_logic_C.9 U13_U_logic_C.8 | length 4978.5
  Top Layer w15: P1.27@318,1429 576,1429 615,1390 899,1390 P2.16@949,1340 v1(2615,1340) ; v1(3100,3505) U13_U_logic_C.8@3100,3588.9
  Bottom Layer w15: v1(2615,1340) 2615,2815 2715,2915 2895,2915 2960,2980 2960,3325 3100,3465 v1(3100,3505) ; v1@3099.41,3505.59 R29_U_logic_C.9@3099.41,3595
BI_23: P1.28 P2.18 R29_U_logic_C.2 U13_U_logic_C.11 U15_U_logic_C.8 | length 6634.5
  Top Layer w15: P1.28@318,1537 593,1537 640,1490 899,1490 P2.18@949,1440 v1(2665,1440) ; v1(3200,3830) U13_U_logic_C.11@3200,3951.1 ; U15_U_logic_C.8@3855,3867.36 v1(3855,3935)
  Bottom Layer w15: v1(2665,1440) 2665,2590 2730,2655 2795,2655 2815,2675 2815,2770 2955,2910 3010,2965 3010,3295 3150,3435 3150,3725 3165,3740 ; R29_U_logic_C.2@2749.41,3595 2749.41,3709.41 2780,3740 3165,3740 ; v1(3855,3935) 3855,3900 3825,3870 3785,3870 3685,3970 3230,3970 3200,3940 v1(3200,3830) 3200,3775 3165,3740
BI_24: P1.29 P2.20 R29_U_logic_D.3 U13_U_logic_D.2 | length 3543.8
  Top Layer w15: P1.29@318,1645 610,1645 667,1588 901,1588 P2.20@949,1540 v1(2800,1540) ; v1(2800,2385) U13_U_logic_D.2@2800,2468.9
  Bottom Layer w15: v1@2799.41,2385.59 R29_U_logic_D.3@2799.41,2475 ; v1(2800,1540) v1(2800,2385)
BI_25: P1.30 P2.22 R29_U_logic_D.4 U13_U_logic_D.3 | length 3497.1
  Top Layer w15: P1.30@318,1753 622,1753 685,1690 899,1690 P2.22@949,1640 v1(2850,1640) ; v1(2850,2385) U13_U_logic_D.3@2850,2468.9
  Bottom Layer w15: v1@2849.41,2385.59 R29_U_logic_D.4@2849.41,2475 ; v1(2850,1640) v1(2850,2385)
BI_26: P1.31 P2.24 R29_U_logic_D.5 U13_U_logic_D.4 | length 3450.4
  Top Layer w15: P1.31@318,1861 634,1861 705,1790 899,1790 P2.24@949,1740 v1(2900,1740) ; v1(2900,2385) U13_U_logic_D.4@2900,2468.9
  Bottom Layer w15: v1@2899.41,2385.59 R29_U_logic_D.5@2899.41,2475 ; v1(2900,1740) v1(2900,2385)
BI_27: P1.32 P2.26 R29_U_logic_D.6 U13_U_logic_D.5 | length 3403.7
  Top Layer w15: P1.32@318,1969 646,1969 725,1890 899,1890 P2.26@949,1840 v1(2950,1840) ; v1(2950,2385) U13_U_logic_D.5@2950,2468.9
  Bottom Layer w15: v1@2949.41,2385.59 R29_U_logic_D.6@2949.41,2475 ; v1(2950,1840) v1(2950,2385)
BI_28: P1.33 P2.28 R29_U_logic_D.7 U13_U_logic_D.6 | length 3357.1
  Top Layer w15: P1.33@318,2077 653,2077 740,1990 899,1990 P2.28@949,1940 v1(3000,1940) ; v1(3000,2385) U13_U_logic_D.6@3000,2468.9
  Bottom Layer w15: v1@2999.41,2385.59 R29_U_logic_D.7@2999.41,2475 ; v1(3000,1940) v1(3000,2385)
BI_29: P1.34 P2.30 R29_U_logic_D.8 U13_U_logic_D.7 | length 3310.4
  Top Layer w15: P1.34@318,2185 660,2185 755,2090 899,2090 P2.30@949,2040 v1(3050,2040) ; v1(3050,2385) U13_U_logic_D.7@3050,2468.9
  Bottom Layer w15: v1@3049.41,2385.59 R29_U_logic_D.8@3049.41,2475 ; v1(3050,2040) v1(3050,2385)
BI_30: P1.35 P2.32 R29_U_logic_D.9 U13_U_logic_D.8 | length 3263.7
  Top Layer w15: P1.35@318,2293 667,2293 770,2190 899,2190 P2.32@949,2140 v1(3100,2140) ; v1(3100,2385) U13_U_logic_D.8@3100,2468.9
  Bottom Layer w15: v1@3099.41,2385.59 R29_U_logic_D.9@3099.41,2475 ; v1(3100,2140) v1(3100,2385)
BI_31: P1.36 P2.34 R29_U_logic_D.2 U13_U_logic_D.11 U15_U_logic_D.8 | length 4916.2
  Top Layer w15: P1.36@318,2401 684,2401 795,2290 899,2290 P2.34@949,2240 v1(3150,2240) ; v1(3200,2710) U13_U_logic_D.11@3200,2831.1 ; U15_U_logic_D.8@3855,2747.36 v1(3855,2815)
  Bottom Layer w15: R29_U_logic_D.2@2749.41,2475 2749.41,2529.41 2790,2570 3150,2570 ; v1(3150,2240) 3150,2620 3200,2670 v1(3200,2710) 3200,2820 3230,2850 3685,2850 3785,2750 3825,2750 3855,2780 v1(3855,2815)
BO_0: P3.2 R31_U_logic_A.16 | length 3405.5
  Top Layer w15: R31_U_logic_A.16@4803.94,6142 v1(4879,6142)
  Bottom Layer w15: v1(4879,6142) 5433,6142 5785,5790 7983,5790 P3.2@8040,5733
BO_1: P3.3 R31_U_logic_A.15 | length 3429.5
  Top Layer w15: R31_U_logic_A.15@4803.94,6092 v1(4879,6092)
  Bottom Layer w15: v1(4879,6092) 5423,6092 5770,5745 7920,5745 P3.3@8040,5625
BO_2: P3.4 R31_U_logic_A.14 | length 3453.9
  Top Layer w15: R31_U_logic_A.14@4803.94,6042 v1(4879,6042)
  Bottom Layer w15: v1(4879,6042) 5418,6042 5865,5595 7961,5595 P3.4@8040,5516
BO_3: P3.5 R31_U_logic_A.13 | length 3484
  Top Layer w15: R31_U_logic_A.13@4803.94,5992 v1(4879,5992)
  Bottom Layer w15: v1(4879,5992) 5413,5992 5850,5555 7905,5555 8040,5420 P3.5@8040,5409
BO_4: P3.6 R31_U_logic_A.12 | length 3515.2
  Top Layer w15: R31_U_logic_A.12@4803.94,5942 v1(4879,5942)
  Bottom Layer w15: v1(4879,5942) 5413,5942 5845,5510 6518.33,5510 6521.33,5513 7847,5513 8040,5320 P3.6@8040,5301
BO_5: P3.7 R31_U_logic_A.11 | length 3525.6
  Top Layer w15: R31_U_logic_A.11@4803.94,5892 v1(4878,5892)
  Bottom Layer w15: v1(4878,5892) 5408,5892 5873,5427 7806,5427 P3.7@8040,5193
BO_6: P3.8 R31_U_logic_A.10 | length 3614.3
  Top Layer w15: R31_U_logic_A.10@4771.46,5842 v1(4878,5842)
  Bottom Layer w15: v1(4878,5842) 5403,5842 5850,5395 7785,5395 7909,5271 7909,5216 P3.8@8040,5085
BO_7: P3.9 R31_U_logic_A.9 | length 3699.4
  Top Layer w15: R31_U_logic_A.9@4803.94,5792 v1(4879,5792)
  Bottom Layer w15: v1(4879,5792) 5404.67,5792 5660,5536.67 5660,5435 5740,5355 7775,5355 7870,5260 7870,5147 P3.9@8040,4977
BO_8: P3.10 R31_U_logic_B.16 | length 3504.2
  Top Layer w15: R31_U_logic_B.16@4776.46,5070 v1(4887,5070)
  Bottom Layer w15: v1(4887,5070) 5405,5070 5795,4680 7735,4680 7925,4870 8039,4870 P3.10@8040,4869
BO_9: P3.11 R31_U_logic_B.15 | length 3471.1
  Top Layer w15: R31_U_logic_B.15@4776.46,5020 v1(4886,5020)
  Bottom Layer w15: v1(4886,5020) 5410,5020 5790,4640 7750,4640 7871,4761 P3.11@8040,4761
BO_10: P3.12 R31_U_logic_B.14 | length 3438.8
  Top Layer w15: R31_U_logic_B.14@4776.46,4970 v1(4886,4970)
  Bottom Layer w15: v1(4886,4970) 5415,4970 5785,4600 7780,4600 7833,4653 P3.12@8040,4653
BO_11: P3.13 R31_U_logic_B.13 | length 3476.9
  Top Layer w15: R31_U_logic_B.13@4776.46,4920 v1(4887,4920)
  Bottom Layer w15: v1(4887,4920) 5415,4920 5860,4475 7820,4475 7890,4545 P3.13@8040,4545
BO_12: P3.14 R31_U_logic_B.12 | length 3442.9
  Top Layer w15: R31_U_logic_B.12@4776.46,4870 v1(4886,4870)
  Bottom Layer w15: v1(4886,4870) 5420,4870 5850,4440 8037,4440 P3.14@8040,4437
BO_13: P3.15 R31_U_logic_B.11 | length 3466.9
  Top Layer w15: R31_U_logic_B.11@4776.46,4820 v1(4886,4820)
  Bottom Layer w15: v1(4886,4820) 5415,4820 5825,4410 7959,4410 P3.15@8040,4329
BO_14: P3.16 R31_U_logic_B.10 | length 3504.9
  Top Layer w15: R31_U_logic_B.10@4776.46,4770 v1(4886,4770)
  Bottom Layer w15: v1(4886,4770) 5410,4770 5800,4380 6470,4380 6527,4323 7915,4323 7938,4323 P3.16@8040,4221 P3.16@8040,4235
BO_15: P3.17 R31_U_logic_B.9 | length 3515
  Top Layer w15: R31_U_logic_B.9@4776.46,4720 v1(4887,4720)
  Bottom Layer w15: v1(4887,4720) 5405,4720 5815,4310 6495,4310 6510,4295 7858,4295 P3.17@8040,4113
BO_16: P3.21 R31_U_logic_C.16 | length 4953.4
  Top Layer w15: R31_U_logic_C.16@4776.46,3940 R31_U_logic_C.16@4808.94,3940 v1(4886,3940) ; v1(7010,4255) v1(7010,5675)
  MidLayer1 w15: v1(7010,5675) 7045,5710 7815,5710 7846,5679 P3.21@8152,5679
  Bottom Layer w15: v1(4886,3940) 5510.67,3940 5825.67,4255 v1(7010,4255)
BO_17: P3.22 R31_U_logic_C.15 | length 4960.8
  Top Layer w15: R31_U_logic_C.15@4776.46,3890 v1(4887,3890) ; v1(7050,4220) v1(7050,5640)
  MidLayer1 w15: v1(7050,5640) 7090,5640 7159,5571 P3.22@8152,5571
  Bottom Layer w15: v1(4887,3890) 5509,3890 5839,4220 v1(7050,4220)
BO_18: P3.23 R31_U_logic_C.14 | length 4892.8
  Top Layer w15: R31_U_logic_C.14@4776.46,3840 v1(4887,3840) ; v1(7085,4170) v1(7085,4825)
  MidLayer1 w15: v1(7085,4825) 7085,4890 ; 7085,4889 7066,4908 7066,4965.68 7085,4984.68 7085,5475 7125,5515 7445,5515 7497,5463 P3.23@8152,5463
  Bottom Layer w15: v1(4887,3840) 5506,3840 5861,4195 6980,4195 7005,4170 v1(7085,4170)
BO_19: P3.24 R31_U_logic_C.13 | length 4765.2
  Top Layer w15: R31_U_logic_C.13@4776.46,3790 v1(4887,3790) ; v1@7120,4870 v1(7125,4870) 7125,4125 v1(7121,4121)
  MidLayer1 w15: v1@7120,4870 v1(7125,4870) 7170,4915 7170,4980 7125,5025 7125,5310 7170,5355 P3.24@8152,5355
  Bottom Layer w15: v1(4887,3790) 5503,3790 5830,4117 6527.67,4117 6530.67,4120 7120,4120 v1(7121,4121)
BO_20: P3.25 R31_U_logic_C.12 | length 4672.9
  Top Layer w15: R31_U_logic_C.12@4776.46,3740 v1(4887,3740) ; v1(7165,4090) 7165,4890 7175,4900 7175,4985 7165,4995 v1(7165,5225)
  MidLayer1 w15: v1(7165,5225) 7874,5225 7896,5247 P3.25@8152,5247
  Bottom Layer w15: v1(4887,3740) 5500,3740 5840,4080 7155,4080 v1(7165,4090)
BO_21: P3.26 R31_U_logic_C.11 | length 4610.7
  Top Layer w15: R31_U_logic_C.11@4776.46,3690 v1(4887,3690) ; v1(7205,4055) v1(7205,5139)
  MidLayer1 w15: v1(7205,5139) P3.26@8152,5139
  Bottom Layer w15: v1(4887,3690) 5490,3690 5855,4055 v1(7205,4055)
BO_22: P3.27 R31_U_logic_C.10 | length 4641.7
  Top Layer w15: R31_U_logic_C.10@4776.46,3640 v1(4887,3640) ; v1(7240,4015) v1(7240,5050)
  MidLayer1 w15: v1(7240,5050) 7285,5095 7961.41,5095 8019.91,5036.5 8060.09,5036.5 8097.08,5073.49 8109.51,5073.49 P3.27@8152,5031
  Bottom Layer w15: v1(4887,3640) 5480,3640 5855,4015 v1(7240,4015)
BO_23: P3.28 R31_U_logic_C.9 | length 4666.4
  Top Layer w15: R31_U_logic_C.9@4776.46,3590 v1(4887,3590) ; v1(7280,3978) v1(7280,4895)
  MidLayer1 w15: v1(7280,4895) 7280,5010 7313,5043 7430.33,5043 7501.33,4972 7976.41,4972 8019.91,4928.5 8060.09,4928.5 8097.08,4965.49 8109.51,4965.49 P3.28@8152,4923
  Bottom Layer w15: v1(4887,3590) 5470,3590 5863,3983 6678.67,3983 6683.67,3978 v1(7280,3978)
BO_24: P3.29 R31_U_logic_D.16 | length 4755.2
  Top Layer w15: R31_U_logic_D.16@4776.46,2820 R31_U_logic_D.16@4808.94,2820 v1(4887,2820)
  MidLayer1 w15: v1(7010,3460) 7390,3460 7610,3680 7610,4575 7850,4815 P3.29@8152,4815
  Bottom Layer w15: v1(4887,2820) 5305,2820 5675,3190 6230,3190 6535,3495 6975,3495 v1(7010,3460)
BO_25: P3.30 R31_U_logic_D.15 | length 4690.4
  Top Layer w15: R31_U_logic_D.15@4776.46,2770 v1(4886,2770)
  MidLayer1 w15: v1(7050,3410) 7060,3410 7380,3410 7640,3670 7640,4545 7802,4707 P3.30@8152,4707
  Bottom Layer w15: v1(4886,2770) 5315,2770 5702.82,3157.82 6317.82,3157.82 6520,3360 7000,3360 v1(7050,3410)
BO_26: P3.31 R31_U_logic_D.14 | length 4596.1
  Top Layer w15: R31_U_logic_D.14@4776.46,2720 v1(4887,2720)
  MidLayer1 w15: v1(7085,3360) 7390,3360 7670,3640 7670,4395 7795,4520 7874,4599 P3.31@8152,4599
  Bottom Layer w15: v1(4887,2720) 5315,2720 5670,3075 5720,3125 5780,3125 6345,3125 6540,3320 7045,3320 v1(7085,3360)
BO_27: P3.32 R31_U_logic_D.13 | length 4619.7
  Top Layer w15: R31_U_logic_D.13@4776.46,2670 v1(4887,2670)
  MidLayer1 w15: v1(7120,3310) 7465,3310 7775,3620 7775,3710 7769,3716 7769,3724.67 7760,3733.67 7760,4420 7831,4491 P3.32@8152,4491
  Bottom Layer w15: v1(4887,2670) 5345,2670 5660,2985 5683,2985 5793.74,3095.74 6440.74,3095.74 6640,3295 7103.21,3295 7118.21,3310 v1(7120,3310)
BO_28: P3.33 R31_U_logic_D.12 | length 4538.3
  Top Layer w15: R31_U_logic_D.12@4776.46,2620 v1(4887,2620)
  MidLayer1 w15: v1(7165,3255) 7195,3285 7395,3285 7415,3265 7465,3265 7840,3640 7840,4350 7873,4383 P3.33@8152,4383
  Bottom Layer w15: v1(4887,2620) 5375,2620 5650,2895 5745,2990 6390,2990 6615,3215 7125,3215 v1(7165,3255)
BO_29: P3.34 R31_U_logic_D.11 | length 4537.9
  Top Layer w15: R31_U_logic_D.11@4776.46,2570 v1(4887,2570)
  MidLayer1 w15: v1(7220,3205) 7615,3205 7875,3465 7875,4240 7910,4275 P3.34@8152,4275
  Bottom Layer w15: v1(4887,2570) 5375,2570 5415,2610 5760,2955 6483.67,2955 6543,3014.33 6543,3018 6705,3180 7195,3180 v1(7220,3205)
BO_30: P3.35 R31_U_logic_D.10 | length 4444.4
  Top Layer w15: R31_U_logic_D.10@4776.46,2520 v1(4887,2520)
  MidLayer1 w15: v1(7240,3160) 7630,3160 7920,3450 7920,4110 7977,4167 P3.35@8152,4167
  Bottom Layer w15: v1(4887,2520) 5370,2520 5775,2925 6520,2925 6725,3130 7210,3130 v1(7240,3160)
BO_31: P3.36 R31_U_logic_D.9 | length 4385.2
  Top Layer w15: R31_U_logic_D.9@4776.46,2470 v1(4887,2470)
  MidLayer1 w15: v1(7280,3120) 7645,3120 7955,3430 7955,4030 7984,4059 P3.36@8152,4059
  Bottom Layer w15: v1(4887,2470) 5360,2470 5775,2885 6530,2885 6735,3090 7250,3090 v1(7280,3120)
C1: U8_24dB_c.1 U8_24dB_c.9 U13_U_logic_C.19 U14_U_logic_C.1 | length 1893.9
  Top Layer w12: U8_24dB_c.9@2443.78,4442.36 2443.95,4442.53 2477.87,4442.53 2487.34,4452 2572.86,4452 2584.86,4440 v1(2590,4440) ; v1(2605,4263.23) U8_24dB_c.1@2666.22,4263.23
  Top Layer w15: v1(2605,4263.23) 2605,4220 2800,4025 ; U13_U_logic_C.19@2800,3951.1 2800,4025 ; U14_U_logic_C.1@3715,3867.36 3715,4025 3690,4050 2825,4050 2800,4025
  MidLayer1 w12: v1(2590,4440) 2615,4415 2615,4278.37 2605,4268.37 v1(2605,4263.23)
C2: U8_12dB_c.1 U8_12dB_c.9 U13_U_logic_C.18 U14_U_logic_C.16 | length 2810.4
  Top Layer w12: U8_12dB_c.9@3413.78,4442.36 3413.95,4442.53 3447.87,4442.53 3457.34,4452 3542.86,4452 3554.86,4440 v1(3560,4440) ; v1(3575,4263.23) U8_12dB_c.1@3636.22,4263.23
  Top Layer w15: U13_U_logic_C.18@2850,3951.1 v1(2850,3830) 2850,3770 2920,3700 3210,3700 3255,3655 3255,3570 3285,3540 3700,3540 3715,3555 U14_U_logic_C.16@3715,3662.64
  MidLayer1 w12: v1(3560,4440) 3585,4415 3585,4278.37 3575,4268.37 v1(3575,4263.23)
  MidLayer1 w15: v1(2850,3830) 2850,4160 2940,4250 3561.77,4250 v1(3575,4263.23)
C3: U8_6dB_c.1 U8_6dB_c.9 U13_U_logic_C.17 U14_U_logic_C.9 | length 3076.7
  Top Layer w12: U8_6dB_c.9@4383.78,4442.36 4383.95,4442.53 4417.87,4442.53 4427.34,4452 4512.86,4452 4524.86,4440 v1(4530,4440) ; v1(4545,4263.23) U8_6dB_c.1@4606.22,4263.23
  Top Layer w15: U13_U_logic_C.17@2900,3951.1 v1(2900,3860) 2900,3770 2935,3735 3220,3735 3292.36,3662.64 U14_U_logic_C.9@3365,3662.64
  MidLayer1 w12: v1(4530,4440) 4555,4415 4555,4278.37 4545,4268.37 v1(4545,4263.23)
  MidLayer1 w15: v1(2900,3860) 2900,4145 2965,4210 3541.33,4210 3542.33,4211 4491,4211 v1@4544.11,4264.11
C4: U8_3dB_c.1 U8_3dB_c.9 U13_U_logic_C.16 U14_U_logic_C.8 | length 4042.8
  Top Layer w12: U8_3dB_c.9@5353.78,4442.36 5353.95,4442.53 5387.87,4442.53 5397.34,4452 5482.86,4452 5494.86,4440 v1(5500,4440) ; v1(5515,4263.23) U8_3dB_c.1@5576.22,4263.23
  Top Layer w15: v1(2950,3830) U13_U_logic_C.16@2950,3951.1 2950,4015 2960,4025 3350,4025 3365,4010 U14_U_logic_C.8@3365,3867.36
  MidLayer1 w12: v1(5500,4440) 5525,4415 5525,4278.37 5515,4268.37 v1(5515,4263.23)
  MidLayer1 w15: v1(2950,3830) 2950,4065 2970,4085 5336.77,4085 v1(5515,4263.23)
C5: U2_PZ1_c.1 U2_PZ1_c.9 U13_U_logic_C.15 U15_U_logic_C.1 | length 5315.9
  Top Layer w12: v1(5530,4040) 5675.43,3894.57 U2_PZ1_c.1@5773.78,3894.57 ; v1(5900,3695) 5920.43,3715.43 U2_PZ1_c.9@5996.22,3715.43
  Top Layer w15: v1(3000,3860) U13_U_logic_C.15@3000,3951.1 ; U15_U_logic_C.1@4205,3867.36 v1(4205,3940)
  MidLayer1 w15: v1(3000,3860) 3000,4030 3030,4060 5513.21,4060 5530,4043.21 v1(5530,4040) 5755,3815 5845,3815 5870,3790 5870,3725 v1(5900,3695)
  Bottom Layer w15: v1(3000,3860) 3000,4015 3035,4050 4180,4050 4205,4025 v1(4205,3940)
C6: U2_PZ2_c.1 U2_PZ2_c.9 U13_U_logic_C.14 U15_U_logic_C.16 | length 6484.8
  Top Layer w12: v1(6535,3895) 6535.43,3894.57 U2_PZ2_c.1@6608.78,3894.57 ; v1(6735,3695) 6755.43,3715.43 U2_PZ2_c.9@6831.22,3715.43
  Top Layer w15: v1(3050,3830) U13_U_logic_C.14@3050,3951.1 ; U15_U_logic_C.16@4205,3662.64 4227.64,3662.64 4250,3685 v1(4250,3900)
  MidLayer1 w15: v1(3050,3830) 3050,3990 3075,4015 5465,4015 5625,3855 5625,3710 5745,3590 6630,3590 v1(6735,3695) 6705,3725 6705,3790 6680,3815 6615,3815 v1(6535,3895)
  Bottom Layer w15: v1(3050,3830) 3050,4005 3070,4025 4055,4025 4180,3900 v1(4250,3900)
C7: U2_PZ3_c.1 U2_PZ3_c.9 U13_U_logic_C.13 U15_U_logic_C.9 | length 6609.5
  Top Layer w12: v1(7370,3895) 7370.43,3894.57 U2_PZ3_c.1@7443.78,3894.57 ; v1(7570,3695) 7590.43,3715.43 U2_PZ3_c.9@7666.22,3715.43
  Top Layer w15: v1(3100,3860) U13_U_logic_C.13@3100,3951.1 ; v1(3810,3910) 3810,3805 3855,3760 U15_U_logic_C.9@3855,3662.64
  MidLayer1 w15: v1(3100,3860) 3100,3945 3130,3975 5450,3975 5585,3840 5585,3690 5720,3555 7430,3555 v1(7570,3695) 7540,3725 7540,3790 7515,3815 7450,3815 v1(7370,3895)
  Bottom Layer w15: v1(3100,3860) 3100,3970 3125,3995 3725,3995 v1(3810,3910)
D1: U8_24dB_d.1 U8_24dB_d.9 U13_U_logic_D.19 U14_U_logic_D.1 | length 1918.9
  Top Layer w12: U8_24dB_d.9@2443.78,3347.36 2443.95,3347.53 2477.87,3347.53 2487.34,3357 2572.86,3357 2584.86,3345 v1(2590,3345) ; v1(2605,3168.23) U8_24dB_d.1@2666.22,3168.23
  Top Layer w15: v1(2605,3168.23) 2605,3100 2800,2905 ; U13_U_logic_D.19@2800,2831.1 2800,2905 ; U14_U_logic_D.1@3715,2747.36 3715,2905 3690,2930 2825,2930 2800,2905
  MidLayer1 w12: v1(2590,3345) 2615,3320 2615,3183.37 2605,3173.37 v1(2605,3168.23)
